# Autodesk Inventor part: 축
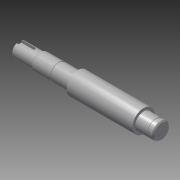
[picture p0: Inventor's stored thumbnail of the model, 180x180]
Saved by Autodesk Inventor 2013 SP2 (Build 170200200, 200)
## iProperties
Created: 2015-12
Part Number: 축
Material: 강철, 연강
Document SubType Name: Modeling
Designer: mduedu
Density: 7.86 g/cm^3
Author: mduedu
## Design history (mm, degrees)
sketch "스케치1"
  geometry: L1 (-64, 0)-(64, 0); L2 (-64, 0)-(-64, 6.5); L3 (-64, 6.5)-(-45, 6.5); L4 (-45, 7)-(-44.134, 7.5); L5 (-44.134, 7.5)-(-11, 7.5); L6 (-11, 7.5)-(-11, 10); L7 (-11, 10)-(48, 10); L8 (48, 10)-(48, 7.5); L9 (48, 7.5)-(64, 7.5); L10 (64, 7.5)-(64, 0); L11 (-45, 6.5)-(-45, 7); 2 further points
  constraints: 22 end point, 6 parallel, 2 perpendicular, 1 coincident, 1 horizontal, 1 midpoint, 1 vertical
  dimensions: "d0" = 13 diameter of L3 L1; "d2" = 15 diameter of L5 L1; "d3" = 20 diameter of L7 L1; "d5" = 15 diameter of L9 L1; "d6" = 128 distance of L1.start L1.end; "d7" = 19 distance of L2.end L3.end; "d8" = 34 distance from line of L6 L3.end; "d9" = 59 distance of L6.end L7.end; "d41" = 14 diameter of L4.start L1; "d42" = 30 deg angle of L4 L3
revolve "회전1" sketch "스케치1" stored, may be unused: angle "d11" = 90 deg
node "작업 평면1"
node "작업 평면2"
sketch "스케치3"
  geometry: L1 (9.5, -2.5)-(-2.5, -2.5); L2 (-2.5, 2.5)-(9.5, 2.5); L3 (9.5, 2.5)-(9.5, -2.5); L4 (9.5, 6.5)-(9.5, -6.5) reference; A1 r 2.5 centre (-2.5, 0) between (-2.5, 2.5) and (-2.5, -2.5); 1 further point
  constraints: 6 end point, 2 point on circle, 2 tangent, 1 centre point, 1 collinear, 1 horizontal, 1 horizontal alignment, 1 parallel
  dimensions: "d17" = 5 distance of L2.end L1.start; "d19" = 12 distance from line of A1.centre L3
extrude "돌출2" cut sketch "스케치3" distance "d20" = 3; taper "d21" = 0 deg
chamfer "모따기1" distance "d22" = 1; stored, may be unused: second distance "d23" = 2, angle "d24" = 45 deg
fillet "모깎기1" dims "d25" = 3
sketch "스케치4"
  geometry: L1 (-11, -10)-(-11, 10) reference; L2 (-11, 0)-(0, 0); L3 (-28.15, 12.15)-(-27, 12.15); L4 (-27, 12.15)-(-27, 7.15); L5 (-27, 7.15)-(-28.15, 7.15); L6 (-28.15, 7.15)-(-28.15, 12.15); L7 (59, 12.15)-(60.15, 12.15); L8 (60.15, 12.15)-(60.15, 7.15); L9 (60.15, 7.15)-(59, 7.15); L10 (59, 7.15)-(59, 12.15); L11 (64, -7.5)-(64, 7.5) reference
  constraints: 18 end point, 4 parallel, 2 horizontal, 2 perpendicular, 1 midpoint
  dimensions: "d26" = 16 distance between parallel lines of L4 L1; "d27" = 1.15 distance of L3.start L3.end; "d28" = 14.3 diameter of L5 L2; "d29" = 5 distance of L3.end L4.end; "d30" = 1.15 distance of L7.start L7.end; "d31" = 5 distance of L7.end L8.end; "d32" = 5 distance between parallel lines of L10 L11; "d33" = 14.3 diameter of L9 L2
revolve "회전2" sketch "스케치4" stored, may be unused: angle "d34" = 90 deg
chamfer "모따기2" distance "d35" = 1; stored, may be unused: second distance "d36" = 2, angle "d37" = 45 deg
sketch "스케치5"
  geometry: 2 further points
  constraints: 1 coincident
sketch "스케치6"
  geometry: 1 further point
hole "구멍1" sketch "스케치6" at (2.5, -3.5) diameter "d43" = 4.917; stored, may be unused: countersink angle "d47" = 90 deg, drill point angle "d49" = 120 deg; dims "d44" = 14, "d45" = 4, "d46" = 2, "d48" = 17
node "솔리드1"
other parameters: "d12" = -15.5
